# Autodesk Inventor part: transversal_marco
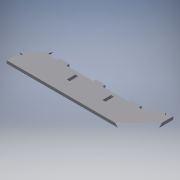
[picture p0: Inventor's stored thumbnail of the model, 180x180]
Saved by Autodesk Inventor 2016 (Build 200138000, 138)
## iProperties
Created: 2017-06
Part Number: transversal_marco
Material: Generic
Document SubType Name: Modeling
Designer: laboratorioesan
Density: 1 g/cm^3
Appearance: Default
Author: laboratorioesan
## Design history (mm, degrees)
sketch "Sketch1"
  geometry: L1 (0, 0)-(0, -60) reference; L2 (0, 0)-(-18.5, 0) reference; L3 (-18.5, -60)-(-18.5, 0) reference; L4 (818.5, 0)-(818.5, -60) reference; L5 (818.5, 0)-(800, 0) reference; L6 (800, -60)-(800, 0) reference; L7 (-18.5, 24.5)-(0, 24.5) reference; L8 (800, 24.5)-(818.5, 24.5) reference; L9 (800, 24.5)-(800, -3) reference; L10 (0, 24.5)-(0, -3) reference; L11 (-18.5, -60)-(818.5, -60); L12 (818.5, -60)-(818.5, 0); L13 (818.5, 0)-(800, 0); L14 (800, 0)-(800, 24.5); L15 (800, 24.5)-(818.5, 24.5); L16 (-18.5, -60)-(-18.5, 0); L17 (-18.5, 0)-(0, 0); L18 (0, 0)-(0, 24.5); L19 (0, 24.5)-(-18.5, 24.5); L20 (818.5, 24.5)-(818.5, 100); L21 (-18.5, 24.5)-(-18.5, 100); L22 (-18.5, 100)-(818.5, 100); L23 (140, 100)-(200, 100); L24 (200, 100)-(200, 118); L25 (200, 118)-(140, 118); L26 (140, 118)-(140, 100); L27 (370, 100)-(430, 100); L28 (430, 100)-(430, 118); L29 (430, 118)-(370, 118); L30 (370, 118)-(370, 100); L31 (600, 100)-(660, 100); L32 (660, 100)-(660, 118); L33 (660, 118)-(600, 118); L34 (600, 118)-(600, 100); L35 (-18.5, 100)-(-18.5, 160); L36 (-18.5, 160)-(100, 100); L37 (818.5, 100)-(818.5, 160); L38 (818.5, 160)-(700, 100); L39 (17.186, 141.931)-(25.317, 157.99); L40 (25.317, 157.99)-(83.308, 128.628); L41 (83.308, 128.628)-(75.177, 112.569); L42 (400, 100)-(400, 38.349); L43 (716.692, 128.628)-(724.823, 112.569); L44 (774.683, 157.99)-(716.692, 128.628); L45 (782.814, 141.931)-(774.683, 157.99); L46 (724.823, 112.569)-(716.692, 128.628); L47 (716.692, 128.628)-(774.683, 157.99); L48 (774.683, 157.99)-(782.814, 141.931); L49 (782.814, 141.931)-(724.823, 112.569); L50 (0, -60)-(-18.5, -60) reference; L51 (818.5, -60)-(800, -60) reference; 1 further point
  constraints: 78 end point, 11 perpendicular, 9 point on line, 7 parallel, 6 collinear, 4 symmetric about line, 4 vertical, 3 horizontal, 2 horizontal alignment, 2 midpoint, 1 vertical alignment
  dimensions: "d0" = 75.5 distance of L8.end L20.end; "d1" = 18 distance of L23.end L24.end; "d2" = 60 distance of L24.end L25.end; "d3" = 170 distance of L29.end L24.end; "d4" = 170 distance of L33.end L28.end; "d5" = 60 distance of L21.end L35.end; "d6" = 40 distance of L23.start L36.end; "d8" = 40 distance of L38.end L31.end; "d9" = 65 distance of L39.end L40.end; "d10" = 18 distance of L39.start L39.end; "d11" = 40 distance of L35.end L39.start
extrude "Extrusion1" new body sketch "Sketch1" distance "d12" = 18.5; taper "d13" = 0 deg
sketch "Sketch2"
  geometry: L1 (75.177, 112.569)-(83.308, 128.628) reference; L2 (83.308, 128.628)-(25.317, 157.99) reference; L3 (25.317, 157.99)-(17.186, 141.931) reference; L4 (17.186, 141.931)-(-18.5, 160) reference; L5 (-18.5, 160)-(-18.5, 24.5) reference; L6 (-18.5, 24.5)-(0, 24.5) reference; L7 (0, 24.5)-(0, 0) reference; L8 (0, 0)-(-18.5, 0) reference; L9 (-18.5, 0)-(-18.5, -60) reference; L10 (-18.5, -60)-(818.5, -60) reference; L11 (818.5, -60)-(818.5, 0) reference; L12 (818.5, 0)-(800, 0) reference; L13 (800, 0)-(800, 24.5) reference; L14 (800, 24.5)-(818.5, 24.5) reference; L15 (818.5, 24.5)-(818.5, 160) reference; L16 (818.5, 160)-(782.814, 141.931) reference; L17 (782.814, 141.931)-(774.683, 157.99) reference; L18 (774.683, 157.99)-(716.692, 128.628) reference; L19 (716.692, 128.628)-(724.823, 112.569) reference; L20 (724.823, 112.569)-(700, 100) reference; L21 (700, 100)-(660, 100) reference; L22 (660, 100)-(660, 118) reference; L23 (660, 118)-(600, 118) reference; L24 (600, 118)-(600, 100) reference; L25 (600, 100)-(430, 100) reference; L26 (430, 100)-(430, 118) reference; L27 (430, 118)-(370, 118) reference; L28 (370, 118)-(370, 100) reference; L29 (370, 100)-(200, 100) reference; L30 (200, 100)-(200, 118) reference; L31 (200, 118)-(140, 118) reference; L32 (140, 118)-(140, 100) reference; L33 (140, 100)-(100, 100) reference; L34 (100, 100)-(75.177, 112.569) reference; L35 (350, -60)-(450, -60) reference; L36 (277.5, 80)-(296, 80); L37 (296, 80)-(296, 25); L38 (296, 25)-(277.5, 25); L39 (277.5, 25)-(277.5, 80); L40 (504, 80)-(522.5, 80); L41 (522.5, 80)-(522.5, 25); L42 (522.5, 25)-(504, 25); L43 (504, 25)-(504, 80); L44 (430, 118)-(370, 118) reference; L45 (400, 118)-(400, 143.309); 1 further point
  constraints: 20 end point, 4 parallel, 3 horizontal, 3 perpendicular, 2 equal length, 2 horizontal alignment, 1 midpoint, 1 point on line, 2 other
  dimensions: "d14" = 18.5 distance of L41.end L42.end; "d15" = 55 distance of L40.end L41.end; "d18" = 245 distance of L41.end L38.end; "d19" = 122.5 horizontal distance of L45.start L36.start; "d20" = 20 distance from line of L29 L36.end
extrude "Extrusion2" cut sketch "Sketch2" distance "d21" = 18.5; taper "d22" = 0 deg
body "Solid1"
node "Reference1"
node "Reference2"
node "Reference3"
node "Reference4"
node "Reference5"
node "Reference6"
node "Projected Loop1"
